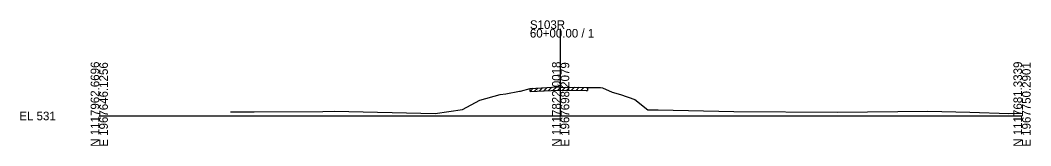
# Model space of a CAD drawing. Extents: x 974 to 1303, y 990 to 10019.
# Drawn here: x 974.3 to 1302.8, y 2490.3 to 2531.1 of the extents above; entities that cross this region are included whole.
import ezdxf

# ---------------------------------------------------------------- set-up
doc = ezdxf.new("R2010")
doc.units = 0
for name, color, linetype in [('Level 10', 7, 'Continuous'), ('Level 60', 7, 'Continuous'), ('Level 61', 7, 'Continuous'), ('Level 63', 7, 'Continuous')]:
    doc.layers.add(name, color=color, linetype=linetype)

msp = doc.modelspace()

# ---------------------------------------------------------------- linework, layer by layer
at = {"layer": 'Level 60'}
for p, q in [((1123.71, 2505.15), (1130.35, 2506.94)), ((1130.35, 2506.94), (1132.16, 2507.25)), ((1132.16, 2507.25), (1136.61, 2508.07)), ((1136.61, 2508.07), (1136.97, 2508.07)), ((1136.97, 2508.07), (1140.05, 2508.95)), ((1140.05, 2508.95), (1149.23, 2509.43)), ((1149.23, 2509.43), (1149.52, 2509.43)), ((1149.52, 2509.43), (1150, 2509.42)), ((1150, 2509.42), (1158.31, 2509.28)), ((1158.31, 2509.28), (1158.7, 2509.28)), ((1158.7, 2509.28), (1162.93, 2509.23)), ((1162.93, 2509.23), (1163.59, 2509.11)), ((1163.59, 2509.11), (1166.7, 2507.74)), ((1166.7, 2507.74), (1169.47, 2507.03)), ((1169.47, 2507.03), (1174.11, 2505.31)), ((1118.07, 2502.06), (1123.71, 2505.15)), ((1174.11, 2505.31), (1178.39, 2502.02)), ((1042.65, 2501.32), (1050.38, 2501.37)), ((1050.38, 2501.37), (1072.64, 2501.48)), ((1072.64, 2501.48), (1076.48, 2501.57)), ((1076.48, 2501.57), (1109.22, 2500.84)), ((1109.22, 2500.84), (1118.07, 2502.06)), ((1178.39, 2502.02), (1181.69, 2502.04)), ((1181.69, 2502.04), (1206.29, 2501.44)), ((1206.29, 2501.44), (1239.98, 2501.28)), ((1239.98, 2501.28), (1269.35, 2501.59)), ((1269.35, 2501.59), (1282.97, 2501.22)), ((1282.97, 2501.22), (1295.75, 2500.86)), ((1295.75, 2500.86), (1300, 2500.94))]:
    msp.add_line(p, q, dxfattribs=at)
at = {"layer": 'Level 61'}
for p, q in [((1140.05, 2507.95), (1141.1, 2509)), ((1140.05, 2507.95), (1140.05, 2508.95)), ((1140.05, 2507.95), (1149.23, 2508.43)), ((1140.05, 2507.95), (1140.05, 2507.95)), ((1141.55, 2508.03), (1142.6, 2509.08)), ((1143.05, 2508.11), (1144.1, 2509.16)), ((1144.55, 2508.18), (1145.6, 2509.24)), ((1146.05, 2508.26), (1147.1, 2509.32)), ((1147.55, 2508.34), (1148.6, 2509.4)), ((1149.05, 2508.42), (1150.04, 2509.42)), ((1149.23, 2508.43), (1149.52, 2508.43)), ((1149.52, 2508.43), (1150, 2508.42)), ((1150, 2508.42), (1158.31, 2508.28)), ((1150.55, 2508.41), (1151.53, 2509.39)), ((1152.05, 2508.38), (1153.03, 2509.37)), ((1153.55, 2508.36), (1154.53, 2509.34)), ((1155.05, 2508.33), (1156.03, 2509.32)), ((1156.55, 2508.31), (1157.53, 2509.29)), ((1158.31, 2508.28), (1158.7, 2508.28)), ((1158.7, 2509.28), (1158.7, 2508.28)), ((1158.7, 2508.28), (1158.7, 2508.28))]:
    msp.add_line(p, q, dxfattribs=at)
at = {"layer": 'Level 63'}
for p, q in [((1150, 2500), (1150, 2528.3)), ((1000, 2500), (1150, 2500)), ((1150, 2500), (1300, 2500))]:
    msp.add_line(p, q, dxfattribs=at)

# ---------------------------------------------------------------- texts
at = {"layer": 'Level 10'}
msp.add_text('540.42', height=0.9, rotation=90, dxfattribs=at).set_placement((1149.95, 2509.92))
at = {"layer": 'Level 63'}
for s, p in [('S103R', (1140, 2528.3)), ('60+00.00 / 1', (1140, 2525.5)), ('EL 531', (974, 2498.6))]:
    msp.add_text(s, height=2.8, dxfattribs=at).set_placement(p)
for s, p in [('N 1117962.6696', (1000, 2490)), ('E 1967646.1256', (1002.8, 2490)), ('N 1117822.0018', (1150, 2490)), ('E 1967698.2079', (1152.8, 2490)), ('N 1117681.3339', (1300, 2490)), ('E 1967750.2901', (1302.8, 2490))]:
    msp.add_text(s, height=2.8, rotation=90, dxfattribs=at).set_placement(p)

doc.saveas('drawing.dxf')
